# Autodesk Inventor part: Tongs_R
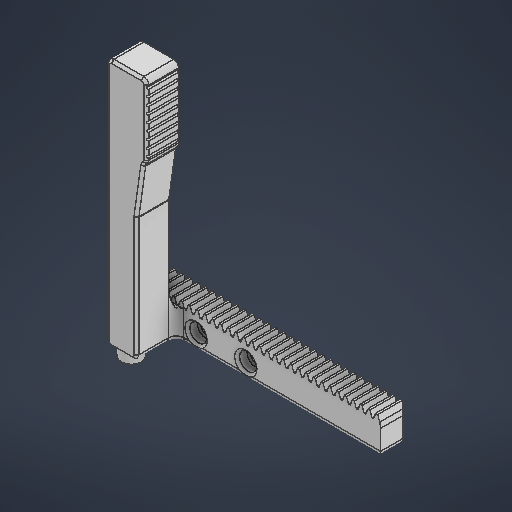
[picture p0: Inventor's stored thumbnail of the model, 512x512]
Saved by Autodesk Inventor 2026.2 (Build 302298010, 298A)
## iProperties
Company: Open CASCADE
Created: 2026-05
Part Number: Tongs_R
Material: 일반
Description: Open CASCADE Model
Document SubType Name: Modeling
Designer: work
Authority: Unknown
Density: 1 g/cm^3
Appearance: 기본값
Sending System: Open CASCADE 7.8
Preprocessor: Open CASCADE STEP processor 7.8
Title: Open CASCADE Shape Model
Author: Author
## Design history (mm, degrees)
feature "기준1"
sketch "스케치1"
  geometry: L1 (0.33, 2)-(1.149, 4.25) reference; L2 (0, 0)-(0.33, 2) reference; L3 (94.248, 0)-(0, 0) reference; L4 (93.917, 2)-(94.248, 0) reference; L5 (93.098, 4.25)-(93.917, 2) reference; L6 (92.256, 4.25)-(93.098, 4.25) reference; L7 (91.437, 2)-(92.256, 4.25) reference; L8 (90.776, 2)-(91.437, 2) reference; L9 (89.957, 4.25)-(90.776, 2) reference; L10 (89.114, 4.25)-(89.957, 4.25) reference; L11 (88.295, 2)-(89.114, 4.25) reference; L12 (87.634, 2)-(88.295, 2) reference; L13 (86.815, 4.25)-(87.634, 2) reference; L14 (85.972, 4.25)-(86.815, 4.25) reference; L15 (85.153, 2)-(85.972, 4.25) reference; L16 (84.493, 2)-(85.153, 2) reference; L17 (83.674, 4.25)-(84.493, 2) reference; L18 (82.831, 4.25)-(83.674, 4.25) reference; L19 (82.012, 2)-(82.831, 4.25) reference; L20 (81.351, 2)-(82.012, 2) reference; L21 (80.532, 4.25)-(81.351, 2) reference; L22 (79.689, 4.25)-(80.532, 4.25) reference; L23 (78.87, 2)-(79.689, 4.25) reference; L24 (78.209, 2)-(78.87, 2) reference; L25 (77.39, 4.25)-(78.209, 2) reference; L26 (76.548, 4.25)-(77.39, 4.25) reference; L27 (75.729, 2)-(76.548, 4.25) reference; L28 (75.068, 2)-(75.729, 2) reference; L29 (74.249, 4.25)-(75.068, 2) reference; L30 (73.406, 4.25)-(74.249, 4.25) reference; L31 (72.587, 2)-(73.406, 4.25) reference; L32 (71.926, 2)-(72.587, 2) reference; L33 (71.107, 4.25)-(71.926, 2) reference; L34 (70.264, 4.25)-(71.107, 4.25) reference; L35 (69.445, 2)-(70.264, 4.25) reference; L36 (68.785, 2)-(69.445, 2) reference; L37 (67.966, 4.25)-(68.785, 2) reference; L38 (67.123, 4.25)-(67.966, 4.25) reference; L39 (66.304, 2)-(67.123, 4.25) reference; L40 (65.643, 2)-(66.304, 2) reference; L41 (64.824, 4.25)-(65.643, 2) reference; L42 (63.981, 4.25)-(64.824, 4.25) reference; L43 (63.162, 2)-(63.981, 4.25) reference; L44 (62.501, 2)-(63.162, 2) reference; L45 (61.682, 4.25)-(62.501, 2) reference; L46 (60.84, 4.25)-(61.682, 4.25) reference; L47 (60.021, 2)-(60.84, 4.25) reference; L48 (59.36, 2)-(60.021, 2) reference; L49 (58.541, 4.25)-(59.36, 2) reference; L50 (57.698, 4.25)-(58.541, 4.25) reference; L51 (56.879, 2)-(57.698, 4.25) reference; L52 (56.218, 2)-(56.879, 2) reference; L53 (55.399, 4.25)-(56.218, 2) reference; L54 (54.556, 4.25)-(55.399, 4.25) reference; L55 (53.738, 2)-(54.556, 4.25) reference; L56 (53.077, 2)-(53.738, 2) reference; L57 (52.258, 4.25)-(53.077, 2) reference; L58 (51.415, 4.25)-(52.258, 4.25) reference; L59 (50.596, 2)-(51.415, 4.25) reference; L60 (49.935, 2)-(50.596, 2) reference; L61 (49.116, 4.25)-(49.935, 2) reference; L62 (48.273, 4.25)-(49.116, 4.25) reference; L63 (47.454, 2)-(48.273, 4.25) reference; L64 (46.793, 2)-(47.454, 2) reference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; 1 further point
  constraints: 8 end point, 2 parallel, 1 horizontal, 1 perpendicular, 1 point on line
  dimensions: "d0" = 10 distance of L123.end L124.end
extrude "돌출1" join sketch "스케치1" stored distance "d1" = 10; taper "d2" = 0 deg
sketch "스케치2"
  geometry: L1 (0.33, 12)-(1.149, 14.25) reference; L2 (0, 10)-(0.33, 12) reference; L3 (0, 10)-(0, 0) reference; L4 (0, 0)-(94.248, 0) reference; L5 (94.248, 0)-(94.248, 10) reference; L6 (93.917, 12)-(94.248, 10) reference; L7 (93.098, 14.25)-(93.917, 12) reference; L8 (92.256, 14.25)-(93.098, 14.25) reference; L9 (91.437, 12)-(92.256, 14.25) reference; L10 (90.776, 12)-(91.437, 12) reference; L11 (89.957, 14.25)-(90.776, 12) reference; L12 (89.114, 14.25)-(89.957, 14.25) reference; L13 (88.295, 12)-(89.114, 14.25) reference; L14 (87.634, 12)-(88.295, 12) reference; L15 (86.815, 14.25)-(87.634, 12) reference; L16 (85.972, 14.25)-(86.815, 14.25) reference; L17 (85.153, 12)-(85.972, 14.25) reference; L18 (84.493, 12)-(85.153, 12) reference; L19 (83.674, 14.25)-(84.493, 12) reference; L20 (82.831, 14.25)-(83.674, 14.25) reference; L21 (82.012, 12)-(82.831, 14.25) reference; L22 (81.351, 12)-(82.012, 12) reference; L23 (80.532, 14.25)-(81.351, 12) reference; L24 (79.689, 14.25)-(80.532, 14.25) reference; L25 (78.87, 12)-(79.689, 14.25) reference; L26 (78.209, 12)-(78.87, 12) reference; L27 (77.39, 14.25)-(78.209, 12) reference; L28 (76.548, 14.25)-(77.39, 14.25) reference; L29 (75.729, 12)-(76.548, 14.25) reference; L30 (75.068, 12)-(75.729, 12) reference; L31 (74.249, 14.25)-(75.068, 12) reference; L32 (73.406, 14.25)-(74.249, 14.25) reference; L33 (72.587, 12)-(73.406, 14.25) reference; L34 (71.926, 12)-(72.587, 12) reference; L35 (71.107, 14.25)-(71.926, 12) reference; L36 (70.264, 14.25)-(71.107, 14.25) reference; L37 (69.445, 12)-(70.264, 14.25) reference; L38 (68.785, 12)-(69.445, 12) reference; L39 (67.966, 14.25)-(68.785, 12) reference; L40 (67.123, 14.25)-(67.966, 14.25) reference; L41 (66.304, 12)-(67.123, 14.25) reference; L42 (65.643, 12)-(66.304, 12) reference; L43 (64.824, 14.25)-(65.643, 12) reference; L44 (63.981, 14.25)-(64.824, 14.25) reference; L45 (63.162, 12)-(63.981, 14.25) reference; L46 (62.501, 12)-(63.162, 12) reference; L47 (61.682, 14.25)-(62.501, 12) reference; L48 (60.84, 14.25)-(61.682, 14.25) reference; L49 (60.021, 12)-(60.84, 14.25) reference; L50 (59.36, 12)-(60.021, 12) reference; L51 (58.541, 14.25)-(59.36, 12) reference; L52 (57.698, 14.25)-(58.541, 14.25) reference; L53 (56.879, 12)-(57.698, 14.25) reference; L54 (56.218, 12)-(56.879, 12) reference; L55 (55.399, 14.25)-(56.218, 12) reference; L56 (54.556, 14.25)-(55.399, 14.25) reference; L57 (53.738, 12)-(54.556, 14.25) reference; L58 (53.077, 12)-(53.738, 12) reference; L59 (52.258, 14.25)-(53.077, 12) reference; L60 (51.415, 14.25)-(52.258, 14.25) reference; L61 (50.596, 12)-(51.415, 14.25) reference; L62 (49.935, 12)-(50.596, 12) reference; L63 (49.116, 14.25)-(49.935, 12) reference; L64 (48.273, 14.25)-(49.116, 14.25) reference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; C1 r 2 at (40, 5.688); C2 r 2 at (20, 5.688); 4 further points
  constraints: 8 end point, 5 point on line, 4 perpendicular, 3 midpoint, 2 centre point, 1 horizontal
  dimensions: "d4" = 0.5625 distance of L126.end point (47.124, 13.688); "d5" = 8 distance of point (47.124, 5.688) point (47.124, 13.688); "d6" = 4 diameter of C1; "d7" = 4 diameter of C2; "d8" = 20 distance of C1.centre C2.centre; "d36" = 20 horizontal distance of point (0, 5) C2.centre
extrude "돌출2" cut sketch "스케치2" extent not by distance; stored distance "d10" = 0; taper "d11" = 0 deg
sketch "스케치3"
  geometry: L1 (0, 0)-(94.248, 0) reference; L2 (0, 0)-(12, 0); L3 (12, 0)-(12, 100); L4 (12, 100)-(0, 100); L5 (12, 100)-(16, 100); L6 (16, 70)-(12, 70); L7 (12, 70)-(12, 100); L8 (16, 97)-(0, 97); L9 (12, 70)-(12, 0); C1 r 0.5 at (0, 97); C2 r 0.5 at (16, 97); C3 r 0.5 at (16, 94); C4 r 0.5 at (0, 94); C5 r 0.5 at (16, 91); C6 r 0.5 at (0, 91); C7 r 0.5 at (16, 88); C8 r 0.5 at (0, 88); C9 r 0.5 at (16, 85); C10 r 0.5 at (0, 85); C11 r 0.5 at (16, 82); C12 r 0.5 at (0, 82); C13 r 0.5 at (16, 79); C14 r 0.5 at (0, 79); C15 r 0.5 at (16, 76); C16 r 0.5 at (0, 76); C17 r 0.5 at (16, 73); C18 r 0.5 at (0, 73); 38 further points
  constraints: 18 centre point, 16 end point, 16 equal radius, 16 vertical alignment, 4 horizontal, 3 vertical, 2 parallel, 1 perpendicular, 8 other
  dimensions: "d12" = 12 distance of L3.end L4.end; "d13" = 100 distance between parallel lines of L1 L4; "d14" = 30 distance of L5.end L6.start; "d15" = 4 distance of L6.start L6.end; "d16" = 1 diameter of C1; "d17" = 1 diameter of C2; "d18" = 3 distance between parallel lines of L4 L8; "d21" = 3 distance of L8.start C3.centre
extrude "돌출3" join sketch "스케치3" distance "d26" = 16; taper "d27" = 0 deg
chamfer "모따기1" distance "d28" = 20; stored, may be unused: second distance "d29" = 2, angle "d30" = 171.887 deg
sketch "스케치4"
  geometry: L1 (0, 10)-(0, 0) reference; L2 (0, 0)-(26, 0) reference; L3 (26, 72.5)-(26, 0) reference; L4 (10, 72.5)-(26, 72.5) reference; L5 (10, 72.5)-(10, 10) reference; L6 (0, 10)-(10, 10) reference; L7 (26, 50)-(10, 10) reference; L8 (13, 20)-(13, 100); L9 (10, 100)-(26, 100) reference; L10 (10, 72.5)-(13, 72.5); L11 (13, 72.5)-(13, 100); L12 (13, 100)-(10, 100); L13 (10, 100)-(10, 72.5); A1 r 18.167 centre (-5.167, 20) between (10, 10) and (13, 20); 3 further points
  constraints: 10 end point, 2 parallel, 2 perpendicular, 2 point on circle, 1 centre point, 1 horizontal, 1 midpoint, 1 point on line, 1 tangent
  dimensions: "d31" = 10 vertical distance of L5.end L8.start; "d32" = 3 horizontal distance of point (10, 41.25) L8.start
extrude "돌출4" cut sketch "스케치4" extent not by distance; stored distance "d33" = 0; taper "d34" = 0 deg
fillet "모깎기1" dims "d35" = 3
chamfer "모따기2" distance "d37" = 2; stored, may be unused: second distance "d38" = 2, angle "d39" = 45 deg
fillet "모깎기2" dims "d40" = 2
chamfer "모따기3" distance "d41" = 1; stored, may be unused: second distance "d42" = 2, angle "d43" = 45 deg
sketch "스케치6"
  geometry: C1 r 2 at (-74.248, 3.688) reference; C2 r 2 at (-54.248, 3.688) reference; 3 further points
  constraints: 2 coincident
hole "구멍1" sketch "스케치6" at (-74.248, 3.688), (-54.248, 3.688) diameter "d44" = 4; stored, may be unused: countersink angle "d48" = 90 deg, drill point angle "d50" = 118 deg; dims "d45" = 6, "d46" = 7, "d47" = 4, "d49" = 8
chamfer "모따기4" distance "d51" = 1; stored, may be unused: second distance "d52" = 2, angle "d53" = 45 deg
sketch "스케치7"
  geometry: L1 (77.248, -7)-(-13, -7) reference; L2 (77.248, 0)-(77.248, -7) reference; L3 (0, 0)-(77.248, 0) reference; L4 (-5, 17)-(-5, 5) reference; L5 (-13, 17)-(-5, 17) reference; L6 (-13, -7)-(-13, 17) reference; L7 (-15, 17)-(-15, -7) reference; L8 (-5, 18)-(-13, 18) reference; C1 r 4 at (-10, 13); A1 r 5 centre (0, 5) between (-5, 5) and (0, 0) reference; 3 further points
  constraints: 1 centre point
  dimensions: "d54" = 8 diameter of C1; "d55" = 5 distance from line of L7 C1.centre; "d56" = 5 distance from line of L8 C1.centre
  node "투영된 루프4"
extrude "돌출5" join sketch "스케치7" distance "d57" = 10; taper "d58" = 0 deg
extrude "돌출6" join sketch "스케치7" distance "d59" = 4; taper "d60" = 0 deg
sketch "스케치8"
  geometry: C1 r 2 at (0, 0); C2 r 4 at (0, 0) reference; 1 further point
  constraints: 1 centre point, 1 concentric
  dimensions: "d61" = 4 diameter of C1
extrude "돌출7" cut sketch "스케치8" distance "d62" = 10; taper "d63" = 0 deg
sketch "스케치9"
  geometry: 1 further point
node "솔리드1"
node "투영된 루프1"
node "투영된 루프2"
node "스케치 - 직사각형 패턴1" dims "d21" = 3, "d24" = 10
node "투영된 루프3"
feature "A9D066F2-1C7D-4E18-AEED-F7BC21143FA4" dims "d44" = 4, "d45" = 6, "d46" = 7, "d47" = 4, "d48" = 90 deg, "d49" = 8, "d50" = 118 deg
